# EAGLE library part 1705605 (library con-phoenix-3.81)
MKDSD 1,5/10-3,81 Printklemme Nennstrom: 8 A Bemessungsspannung: 200 V Raster: 3,81 mm Polzahl: 12 Montageart: Löten Anschlussart: Schraubanschluss Anschlussrichtung vom Leiter zur Platine: 0° Source: http://eshop.phoenixcontact.com .. 1705605.pdf
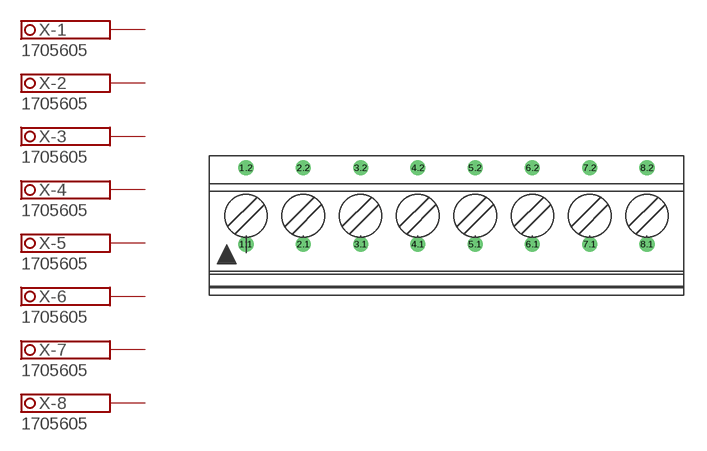
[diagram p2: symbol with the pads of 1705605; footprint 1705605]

Designator prefix X; gates -1=SCHRAUBKLEMME_2 -2=SCHRAUBKLEMME_2 -3=SCHRAUBKLEMME_2 -4=SCHRAUBKLEMME_2 -5=SCHRAUBKLEMME_2 -6=SCHRAUBKLEMME_2 -7=SCHRAUBKLEMME_2 -8=SCHRAUBKLEMME_2

## 1705605 (OC_FARNELL: unknown; OC_NEWARK: unknown)  [1705605]
1.1  -1:1A  pas
1.2  -1:1B  pas
2.1  -2:1A  pas
2.2  -2:1B  pas
3.1  -3:1A  pas
3.2  -3:1B  pas
4.1  -4:1A  pas
4.2  -4:1B  pas
5.1  -5:1A  pas
5.2  -5:1B  pas
6.1  -6:1A  pas
6.2  -6:1B  pas
7.1  -7:1A  pas
7.2  -7:1B  pas
8.1  -8:1A  pas
8.2  -8:1B  pas

## Footprint 1705605 (pad centres in mm)
MKDSD 1,5/ 8-3,81 Printklemme Nennstrom: 8 A Bemessungsspannung: 200 V Raster: 3,81 mm Polzahl: 8 Montageart: Löten Anschlussart: Schraubanschluss Anschlussrichtung vom Leiter zur Platine: 0° Source: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
drill 0.5 pad 0.9 round: 1.1 -13.335,-1.25; 1.2 -13.335,3.83; 2.1 -9.525,-1.25; 2.2 -9.525,3.83; 3.1 -5.715,-1.25; 3.2 -5.715,3.83; 4.1 -1.905,-1.25; 4.2 -1.905,3.83; 5.1 1.905,-1.25; 5.2 1.905,3.83; 6.1 5.715,-1.25; 6.2 5.715,3.83; 7.1 9.525,-1.25; 7.2 9.525,3.83; 8.1 13.335,-1.25; 8.2 13.335,3.83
